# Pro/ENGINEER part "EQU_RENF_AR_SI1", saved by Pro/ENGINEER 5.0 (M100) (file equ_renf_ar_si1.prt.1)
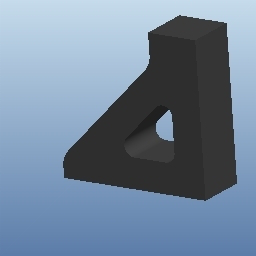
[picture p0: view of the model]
Units: millimeter Newton Second (mmNs); MM, TONNE, HOURS
Materials in the file: NYLON

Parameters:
  PTC_MATERIAL_NAME = "NYLON"

Other named items: DROITE, DESSUS, FACE, CS0

Layers: 03_PLANS, 06_REPERES, 09_ARRONDIS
